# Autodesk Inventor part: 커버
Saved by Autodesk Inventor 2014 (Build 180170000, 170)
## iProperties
Created: 2026-10
Part Number: 커버
Material: 일반
Document SubType Name: Modeling
Designer: dg
Density: 1 g/cm^3
Appearance: 기본값
Author: dg
Author: jhkim
Creation Date: 2026-09-29
Sending System: Autodesk Inventor 2027
Preprocessor: ST-DEVELOPER v20.1
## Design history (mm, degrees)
node "커버1"
node "솔리드1"
node "기준1"
